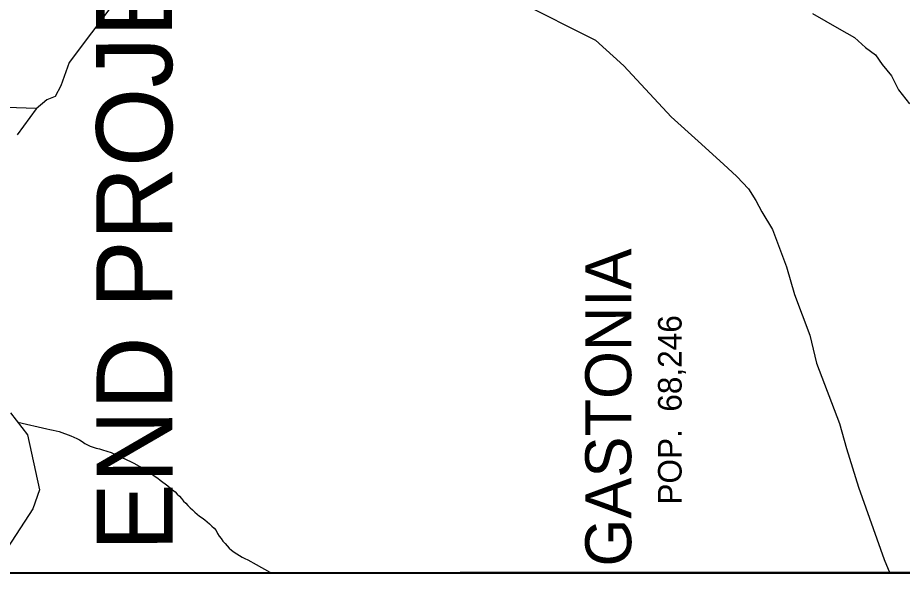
# Model space of a CAD drawing. Extents: x 1373043 to 1375788, y 550128 to 553055.
# Drawn here: x 1373215 to 1373360.4, y 550416.5 to 550507.8 of the extents above; entities that cross this region are included whole.
import ezdxf

# ---------------------------------------------------------------- set-up
doc = ezdxf.new("R2010")
doc.units = 0
for name, color, linetype in [('CTL Sheet Border CELL', 7, 'Continuous'), ('Default', 7, 'Continuous'), ('Old_Level_32', 7, 'Continuous'), ('Old_Level_59', 7, 'Continuous'), ('Old_Level_62', 7, 'Continuous'), ('Old_Level_9', 7, 'Continuous'), ('Prop Dimension Text', 7, 'Continuous')]:
    doc.layers.add(name, color=color, linetype=linetype)

msp = doc.modelspace()

# ---------------------------------------------------------------- linework, layer by layer
at = {"layer": 'CTL Sheet Border CELL'}
msp.add_lwpolyline([(1373086.16, 553025.24), (1373088.48, 550416.54), (1374914.56, 550418.17), (1374912.24, 553026.87)], close=True, dxfattribs=at)
at = {"layer": 'Old_Level_32'}
msp.add_lwpolyline([(1373297.36, 550510.49), (1373310, 550504.11), (1373314.65, 550499.93), (1373322.43, 550491.54), (1373326.88, 550487.52), (1373331.07, 550483.74), (1373333.25, 550481.73), (1373335.18, 550479.72), (1373336.36, 550477.79), (1373337.36, 550475.95), (1373339.12, 550473.01), (1373341.39, 550466.9), (1373342.73, 550462.37), (1373345.25, 550455.66), (1373346.35, 550451.05), (1373350.13, 550441.16), (1373351.25, 550437.04), (1373353.23, 550430.67), (1373357.45, 550418.8), (1373358.4, 550416.54)], dxfattribs=at)
at = {"layer": 'Old_Level_59'}
for points in [[(1373234.34, 550514.91), (1373223.48, 550500.46), (1373222.08, 550496.64), (1373221.15, 550494.88), (1373219.78, 550494.31), (1373218.06, 550492.87), (1373214.93, 550488.57)], [(1373213.84, 550442.9), (1373216.62, 550439.31), (1373218.6, 550430.24), (1373217.49, 550427.15), (1373212.6, 550419.61)]]:
    msp.add_lwpolyline(points, dxfattribs=at)
at = {"layer": 'Old_Level_62'}
for points in [[(1373345.69, 550508.49), (1373347.86, 550507.24), (1373350.06, 550506), (1373352.61, 550504.56), (1373354.39, 550502.95), (1373356.02, 550501.72), (1373357.13, 550500.11), (1373358.66, 550498.26), (1373359.81, 550495.96), (1373361.65, 550493.66)], [(1373217.93, 550492.88), (1373213.3, 550493.09)], [(1373215.04, 550441.35), (1373219.83, 550440.26), (1373220.32, 550440.15), (1373220.83, 550440.04), (1373221.34, 550439.96), (1373221.84, 550439.85), (1373223.76, 550439.11), (1373224.23, 550438.91), (1373224.71, 550438.7), (1373225.17, 550438.47), (1373225.6, 550438.19), (1373226.03, 550437.89), (1373226.48, 550437.63), (1373226.95, 550437.44), (1373227.44, 550437.27), (1373227.94, 550437.12), (1373228.44, 550436.98), (1373228.94, 550436.85), (1373230.36, 550436.38), (1373233.66, 550434.88), (1373234.11, 550434.64), (1373236.34, 550433.35), (1373236.77, 550433.07), (1373237.2, 550432.77), (1373237.62, 550432.47), (1373238.04, 550432.16), (1373238.45, 550431.86), (1373238.86, 550431.54), (1373239.27, 550431.23), (1373239.68, 550430.91), (1373240.09, 550430.59), (1373240.49, 550430.26), (1373240.88, 550429.92), (1373241.25, 550429.57), (1373241.61, 550429.2), (1373241.95, 550428.81), (1373242.29, 550428.41), (1373242.64, 550428.04), (1373243.01, 550427.67), (1373243.38, 550427.31), (1373243.76, 550426.96), (1373244.14, 550426.61), (1373244.53, 550426.27), (1373244.93, 550425.95), (1373245.35, 550425.64), (1373245.76, 550425.33), (1373246.16, 550425), (1373246.55, 550424.66), (1373246.93, 550424.3), (1373247.29, 550423.94), (1373247.64, 550423.56), (1373247.86, 550423.09), (1373248.15, 550422.66), (1373248.45, 550422.24), (1373248.76, 550421.83), (1373249.1, 550421.44), (1373249.44, 550421.05), (1373249.8, 550420.67), (1373250.18, 550420.32), (1373250.6, 550420.02), (1373251.03, 550419.74), (1373251.47, 550419.48), (1373251.92, 550419.22), (1373252.38, 550418.97), (1373252.83, 550418.73), (1373254.21, 550418.01), (1373256.46, 550416.74), (1373256.9, 550416.54)]]:
    msp.add_lwpolyline(points, dxfattribs=at)
at = {"layer": 'Prop Dimension Text'}
msp.add_lwpolyline([(1373088.48, 550913.04), (1373088.48, 550416.54), (1373584.98, 550416.54), (1373584.98, 550913.04)], close=True, dxfattribs=at)

# ---------------------------------------------------------------- texts
at = {"layer": 'Default'}
msp.add_text('END PROJECT', height=12.4955, rotation=90.0509, dxfattribs=at).set_placement((1373240.48, 550420.18))
at = {"layer": 'Old_Level_9'}
for s, height, p in [('GASTONIA', 7.56, (1373315.88, 550417.66)), ('POP.  68,246', 3.8755, (1373324.16, 550427.83))]:
    msp.add_text(s, height=height, rotation=90, dxfattribs=at).set_placement(p)

doc.saveas('drawing.dxf')
